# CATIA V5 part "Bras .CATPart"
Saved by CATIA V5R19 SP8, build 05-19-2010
Part number: Bras 
Bounding box of the stored display mesh (mm): x -1 to 4, y -43.464 to 43.464, z -3.804 to 3.804
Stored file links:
  F:\Projet3\Bras .CATPart
  F:\Projet3\Produit1.CATProduct
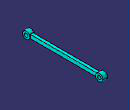
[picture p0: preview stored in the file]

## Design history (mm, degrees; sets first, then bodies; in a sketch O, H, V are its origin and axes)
Parameters
  Longueur = 10 mm
Body1 (main body)
  Sketch1 on yz-plane, origin (0, 0, 0), H (0, 1, 0), V (0, 0, 1)
    point P1 (0, 2)
    line L1 (0, 2) -> (36, 2)
    line L2 (36, 2) -> (36, -2)
    line L3 (36, -2) -> (0, -2)
    point P4 (0, -2)
    line L4 (0, -2) -> (0, 2)
    length L1 = 36 {= Longueur *3.6}
    length L2 = 4 {= Longueur *0.4}
    distance H L3 = 2 {= Longueur *0.2}
    coincidence: P1 V, P4 V
    horizontal: L1 H, L3 H
    vertical: L2 V, L4 V
  Pad1: profile Sketch1, direction (1, 0, 0), length 3 {= Longueur *0.3}
  Sketch2 on end face of Pad1, origin (3, 0, 0), H (0, 1, 0), V (0, 0, 1)
    arc A1 centre (39.4641, 0) radius 4 from (36, 2) to (36, -2) ccw
    point P2 (36, 2)
    point P3 (36, -2)
    reference projected point E1 (36, -2) from vertex [face of Pad1 from Sketch1.L2 | end face of Pad1 | face of Pad1 from Sketch1.L3]
    reference projected point E2 (36, 2) from vertex [face of Pad1 from Sketch1.L1 | end face of Pad1 | face of Pad1 from Sketch1.L2]
    radius A1 = 4 {= Longueur *0.4}
    coincidence: P3 E1, P2 E2
  Pocket1: profile Sketch2, direction (-1, 0, 0), through (limit type 6), offset 0 {= Longueur *0}
  Point1: (4 {= Longueur *0.4}, 0 {= Longueur *0}, 0 {= Longueur *0})
  Plane1: type OffsetPt, RefPlane end face of Pad1, RefPoint Point1
  Sketch3 on Plane1, origin (4, 0, 0), H (0, -1, 0), V (0, 0, 1)
    circle A1 centre (-39.4641, 0) radius 4
    point P1 (-39.4641, 0)
    reference projected arc E1 centre (-39.4641, 0) radius 4 from (-36, -2) to (-36, 2) ccw from edge [face of Pocket1 from Sketch2.A1 | start face of Pad1]
    coincidence: P1 H, A1 E1
  Pad2: profile Sketch3, direction (-1, 0, 0), length 5 {= Longueur *0.5}
  Sketch4 on start face of Pad2, origin (4, 0, 0), H (0, 1, 0), V (0, 0, 1)
    circle A1 centre (39.4641, 0) radius 2
    reference projected circle E1 centre (39.4641, 0) radius 4 from edge [start face of Pad2 | face of Pad2 from Sketch3.A1]
    radius A1 = 2 {= Longueur *0.2}
    concentricity: A1 E1
  Pocket2: profile Sketch4, direction (-1, 0, 0), up to end face of Pad2, offset 0 {= Longueur *0}
  Mirror1: of the body so far, about zx-plane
